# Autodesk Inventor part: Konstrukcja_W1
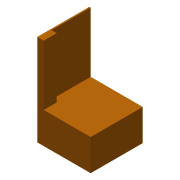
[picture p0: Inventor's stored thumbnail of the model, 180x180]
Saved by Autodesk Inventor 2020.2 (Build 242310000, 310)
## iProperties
Created: 2014-09
Part Number: Konstrukcja_W1
Material: Ogólny
Document SubType Name: Modeling
Designer: F.Stasiak
Density: 1 g/cm^3
Appearance: Pomarańczowa
Catalog Web Link: www.expertbooks.pl
Manager: www.cadconsulting.pl
Company: Fabian Stasiak CAD Consulting
Author: F.Stasiak
Subject: Zbiór ćwiczeń. Autodesk Inventor 2020. Kurs Professional
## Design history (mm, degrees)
sketch "Szkic1"
  geometry: L1 (-100, 100)-(100, 100); L2 (100, 100)-(100, -100); L3 (100, -100)-(-100, -100); L4 (-100, -100)-(-100, 100); L5 (-100, 100)-(100, -100); L6 (100, 100)-(-100, -100); 1 further point
  constraints: 12 end point, 2 midpoint, 2 parallel, 1 horizontal, 1 perpendicular
  dimensions: "d0" = 200 distance of L2.end L3.end; "d1" = 200 distance of L1.end L2.end
extrude "Wyciągnięcie proste1" new body sketch "Szkic1" distance "d2" = 120; taper "d3" = 0 deg
sketch "Szkic2"
  geometry: L1 (0, 0)-(0, 200) reference; L2 (0, 0)-(120, 0) reference; L3 (120, 200)-(120, 0) reference; L4 (0, 200)-(120, 200) reference; L5 (0, 0)-(350, 0); L6 (350, 0)-(350, 200); L7 (350, 200)-(0, 200); L8 (0, 200)-(0, 0); 1 further point
  constraints: 8 end point, 2 parallel, 1 horizontal, 1 perpendicular
  dimensions: "d4" = 350 distance of L7.end L6.end; "d5" = 200 distance of L6.end L5.end
extrude "Wyciągnięcie proste2" join sketch "Szkic2" distance "d6" = 5; taper "d7" = 0 deg
sketch "Szkic3"
  geometry: L1 (-200, 120)-(-200, 350) reference; L2 (-200, 120)-(0, 120) reference; L3 (-200, 350)-(-180, 350); L4 (-180, 350)-(-180, 120); L5 (-180, 120)-(-200, 120); L6 (-200, 120)-(-200, 350); 1 further point
  constraints: 8 end point, 2 parallel, 1 horizontal, 1 perpendicular
  dimensions: "d8" = 20 distance of L4.end L5.end; "d9" = 230 distance of L3.end L4.end
extrude "Wyciągnięcie proste3" join sketch "Szkic3" distance "d10" = 50; taper "d11" = 0 deg
node "Bryła1"
node "Pętla rzutowana1"
